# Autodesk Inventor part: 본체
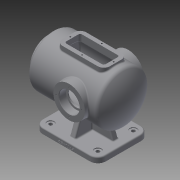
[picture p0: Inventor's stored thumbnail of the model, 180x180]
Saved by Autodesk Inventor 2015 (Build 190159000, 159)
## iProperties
Created: 2021-11
Part Number: 본체
Material: 일반
Document SubType Name: Modeling
Designer: 101698
Mass: 1311.33 g
Surface Area: 2404.16 cm^2
Volume: 1311.33 cm^3
Density: 1 g/cm^3
Appearance: 기본값
Author: 101698
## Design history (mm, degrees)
sketch "스케치1"
  geometry: L1 (-80, -65)-(80, -65); L2 (80, -65)-(80, 65); L3 (80, 65)-(-80, 65); L4 (-80, 65)-(-80, -65); L5 (-80, -65)-(80, 65); L6 (80, -65)-(-80, 65); 1 further point
  constraints: 12 end point, 2 midpoint, 2 parallel, 1 horizontal, 1 perpendicular
  dimensions: "d0" = 160 distance of L1.start L1.end; "d1" = 130 distance of L1.end L2.end
extrude "돌출1" new body sketch "스케치1" distance "d2" = 14; taper "d3" = 0 deg
sketch "스케치2"
  geometry: L1 (-7, -50)-(7, -50); L2 (7, -50)-(7, 50); L3 (7, 50)-(-7, 50); L4 (-7, 50)-(-7, -50); L5 (-7, -50)-(7, 50); L6 (7, -50)-(-7, 50); 1 further point
  constraints: 12 end point, 2 midpoint, 2 parallel, 1 horizontal, 1 perpendicular
  dimensions: "d4" = 14 distance of L2.end L3.end; "d5" = 100 distance of L1.end L2.end
extrude "돌출2" join sketch "스케치2" distance "d6" = 100; taper "d7" = 0 deg
sketch "스케치3"
  geometry: L1 (-7, -50)-(-7, 50) reference; L2 (-7, 50)-(7, 50) reference; L3 (7, 50)-(7, -50) reference; L4 (7, -50)-(-7, -50) reference; L5 (-80, -65)-(-80, 65) reference; L6 (-80, 65)-(80, 65) reference; L7 (80, 65)-(80, -65) reference; L8 (80, -65)-(-80, -65) reference; L9 (-60, -7)-(60, -7); L10 (60, -7)-(60, 7); L11 (60, 7)-(-60, 7); L12 (-60, 7)-(-60, -7); L13 (-60, -7)-(60, 7); L14 (60, -7)-(-60, 7); 1 further point
  constraints: 12 end point, 2 midpoint, 2 parallel, 1 horizontal, 1 perpendicular
  dimensions: "d8" = 14 distance of L11.end L9.start; "d9" = 120 distance of L10.end L11.end
extrude "돌출3" join sketch "스케치3" distance "d10" = 100; taper "d11" = 0 deg
feature "면 기울기1" dims angle "d12" = 20 deg
feature "면 기울기2" dims angle "d13" = 20 deg
feature "면 기울기3" dims angle "d14" = 20 deg
feature "면 기울기4" dims angle "d15" = 20 deg
sketch "스케치8"
  geometry: L1 (-80, 0)-(-80, 14) reference; L2 (-80, 14)-(-60, 14) reference; L3 (-60, 14)-(-23.603, 114) reference; L4 (-23.603, 114)-(23.603, 114) reference; L5 (23.603, 114)-(60, 14) reference; L6 (60, 14)-(80, 14) reference; L7 (80, 14)-(80, 0) reference; L8 (80, 0)-(-80, 0) reference; L9 (-75.993, 179)-(100, 179); L10 (123.314, 91.246)-(-119.568, 136.063); L11 (-109.588, 46.16)-(109.588, 181.84); L12 (-100, 114)-(100, 114); L13 (100, 179)-(100, 114); L14 (80, 0)-(-80, 0) reference; A1 r 95.786 centre (0, 114) between (80, 61.322) and (94.196, 96.619); A2 r 100 centre (0, 114) between (-75.993, 179) and (-100, 114); 2 further points
  constraints: 10 end point, 4 point on circle, 3 midpoint, 3 point on line, 2 centre point, 2 parallel, 1 coincident, 1 horizontal, 1 perpendicular
  dimensions: "d33" = 10 distance of L9.end L11.end; "d34" = 200 distance of L12.start L12.end; "d35" = 65 distance of L9.end L12.end; "d36" = 100 radius of A2; "d142" = 114 vertical distance of L7.end L12.end; "d143" = 20 distance from line of L7 L12.end
revolve "회전1" sketch "스케치8" stored, may be unused: angle "d37" = 90 deg
sketch "스케치10"
  geometry: C1 r 65 at (0, 0) reference; C2 r 47.5 at (0, 0); 1 further point
  constraints: 1 centre point, 1 coincident
  dimensions: "d41" = 95 diameter of C2
extrude "돌출7" join sketch "스케치10" distance "d42" = 10; taper "d43" = 0 deg
sketch "스케치11"
  geometry: C1 r 47.5 at (0, 0) reference; 1 further point
hole "구멍1" sketch "스케치11" at (0, 0) diameter "d44" = 65; stored, may be unused: countersink angle "d48" = 90 deg, drill point angle "d50" = 118 deg; dims "d45" = 6, "d46" = 4, "d47" = 2, "d49" = 40
sketch "스케치12"
  geometry: C1 r 32.5 at (0, 0) reference; 2 further points
  constraints: 1 horizontal alignment
  dimensions: "d51" = 40 distance of C1.centre point (40, 0)
hole "구멍2" sketch "스케치12" at (40, 0) diameter "d52" = 3.242; stored, may be unused: countersink angle "d56" = 90 deg, drill point angle "d58" = 118 deg; dims "d53" = 11, "d54" = 4, "d55" = 2, "d57" = 13
node "작업 평면1"
sketch "스케치13"
  geometry: C1 r 40 at (-17, 114); 1 further point
  constraints: 1 centre point
  dimensions: "d63" = 80 diameter of C1; "d64" = 17 horizontal distance of point (0, 0) C1.centre; "d65" = 114 vertical distance of point (0, 0) C1.centre
extrude "돌출8" join sketch "스케치13" distance "d66" = 150; taper "d67" = 0 deg
node "작업 평면2"
sketch "스케치15"
  geometry: L1 (-60, -30)-(60, -30); L2 (60, -30)-(60, 30); L3 (60, 30)-(-60, 30); L4 (-60, 30)-(-60, -30); L5 (-60, -30)-(60, 30); L6 (60, -30)-(-60, 30); 1 further point
  constraints: 12 end point, 2 midpoint, 2 parallel, 1 horizontal, 1 perpendicular
  dimensions: "d69" = 120 distance of L2.end L3.end; "d70" = 60 distance of L3.end L1.start
extrude "돌출9" join sketch "스케치15" stored distance "d71" = 150; taper "d72" = 0 deg
sketch "스케치16"
  geometry: L1 (-50, -20)-(50, -20); L2 (50, -20)-(50, 20); L3 (50, 20)-(-50, 20); L4 (-50, 20)-(-50, -20); L5 (-50, -20)-(50, 20); L6 (50, -20)-(-50, 20); 1 further point
  constraints: 12 end point, 2 midpoint, 2 parallel, 1 horizontal, 1 perpendicular
  dimensions: "d73" = 100 distance of L2.end L3.end; "d74" = 40 distance of L1.end L2.end
extrude "돌출10" cut sketch "스케치16" distance "d75" = 30; taper "d76" = 0 deg
sketch "스케치17"
  geometry: C1 r 40 at (0, 0) reference; 1 further point
hole "구멍3" sketch "스케치17" at (0, 0) diameter "d77" = 42; stored, may be unused: countersink angle "d81" = 90 deg, drill point angle "d83" = 118 deg; dims "d78" = 11, "d79" = 52, "d80" = 18, "d82" = 13
sketch "스케치18"
  geometry: C1 r 21 at (0, 0) reference; C2 r 40 at (0, 0) reference; C3 r 26 at (0, 0); 1 further point
  constraints: 1 centre point, 1 coincident
  dimensions: "d84" = 52 diameter of C3
extrude "돌출11" cut sketch "스케치18" distance "d85" = 18; taper "d86" = 0 deg
sketch "스케치19"
  geometry: C1 r 26 at (0, 0) reference; 2 further points
  constraints: 1 horizontal alignment
  dimensions: "d87" = 32.5 distance of point (32.5, 0) C1.centre
hole "구멍4" sketch "스케치19" at (32.5, 0) diameter "d88" = 3.242; stored, may be unused: countersink angle "d92" = 90 deg, drill point angle "d94" = 118 deg; dims "d89" = 11, "d90" = 52, "d91" = 18, "d93" = 13
sketch "스케치20"
  geometry: 5 further points
  constraints: 2 horizontal alignment, 1 vertical alignment
  dimensions: "d98" = 25 distance of point (0, 0) point (0, 25); "d99" = 25 distance of point (0, 0) point (0, -25); "d100" = 55 distance of point (0, 0) point (-55, 0); "d101" = 55 distance of point (55, 0) point (0, 0)
hole "구멍5" sketch "스케치20" at (0, 25), (0, -25), (55, 0), (-55, 0) diameter "d102" = 3.242; stored, may be unused: countersink angle "d106" = 90 deg, drill point angle "d108" = 118 deg; dims "d103" = 9, "d104" = 52, "d105" = 18, "d107" = 11
fillet "모깎기1" dims "d109" = 5
fillet "모깎기2" dims "d110" = 15
sketch "스케치21"
  geometry: L1 (-47.261, 49)-(-75.993, 49) reference; L2 (-75.993, 179)-(-60, 179) reference; L3 (-60, 179)-(-60, 184) reference; L4 (-60, 184)-(-56.621, 184) reference; L5 (-56.621, 184)-(-56.621, 173) reference; L6 (-56.621, 173)-(-55, 172.026) reference; L7 (-55, 172.026)-(-53.379, 173) reference; L8 (-53.379, 173)-(-53.379, 184) reference; L9 (-53.379, 184)-(-50, 184) reference; L10 (-50, 184)-(-50, 154) reference; L11 (-50, 154)-(50, 154) reference; L12 (50, 154)-(50, 184) reference; L13 (50, 184)-(53.379, 184) reference; L14 (53.379, 184)-(53.379, 173) reference; L15 (53.379, 173)-(55, 172.026) reference; L16 (55, 172.026)-(56.621, 173) reference; L17 (56.621, 173)-(56.621, 184) reference; L18 (56.621, 184)-(60, 184) reference; L19 (60, 184)-(60, 179) reference; L20 (60, 179)-(100, 179) reference; L21 (100, 179)-(100, 161.5) reference; L22 (100, 161.5)-(110, 161.5) reference; L23 (110, 161.5)-(110, 155.621) reference; L24 (110, 155.621)-(97, 155.621) reference; L25 (97, 155.621)-(96.026, 154) reference; L26 (96.026, 154)-(97, 152.379) reference; L27 (97, 152.379)-(110, 152.379) reference; L28 (110, 152.379)-(110, 146.5) reference; L29 (110, 146.5)-(70, 146.5) reference; L30 (70, 146.5)-(50.472, 114) reference; L31 (50.472, 114)-(70, 81.5) reference; L32 (70, 81.5)-(110, 81.5) reference; L33 (110, 81.5)-(110, 75.621) reference; L34 (110, 75.621)-(97, 75.621) reference; L35 (97, 75.621)-(96.026, 74) reference; L36 (96.026, 74)-(97, 72.379) reference; L37 (97, 72.379)-(110, 72.379) reference; L38 (110, 72.379)-(110, 66.5) reference; L39 (110, 66.5)-(100, 66.5) reference; L40 (100, 66.5)-(100, 49) reference; L41 (100, 49)-(47.261, 49) reference; L42 (47.261, 49)-(60, 14) reference; L43 (60, 14)-(80, 14) reference; L44 (80, 14)-(80, 0) reference; L45 (80, 0)-(-80, 0) reference; L46 (-80, 0)-(-80, 14) reference; L47 (-80, 14)-(-60, 14) reference; L48 (-60, 14)-(-47.261, 49) reference; L49 (85, 114)-(-90, 114); L50 (85, 114)-(85, 169); L51 (85, 169)-(-69.75, 169); C1 r 21 at (-17, 114) reference; A1 r 100 centre (0, 114) between (-75.993, 179) and (-75.993, 49) reference; A2 r 90 centre (0, 114) between (-72.155, 167.793) and (-90, 114); A3 r 3 centre (-69.75, 166) between (-69.75, 169) and (-72.155, 167.793); 2 further points
  constraints: 6 end point, 5 point on circle, 2 centre point, 2 tangent, 1 horizontal, 1 perpendicular, 1 point on line, 1 vertical
  dimensions: "d111" = 10 radial gap between concentric circles of A1 A2; "d112" = 10 distance between parallel lines of L51 L2; "d113" = 15 distance between parallel lines of L21 L50; "d114" = 114 distance between parallel lines of L45 L49; "d116" = 3 radius of A3
revolve "회전2" sketch "스케치21" stored, may be unused: angle "d115" = 90 deg
fillet "모깎기3" dims "d117" = 10
fillet "모깎기4" dims "d118" = 3
fillet "모깎기5" dims "d119" = 10
fillet "모깎기6" dims "d120" = 3
fillet "모깎기7" dims "d121" = 3
fillet "모깎기8" dims "d122" = 3
fillet "모깎기9" dims "d123" = 3
fillet "모깎기10" dims "d124" = 20
sketch "스케치22"
  geometry: A1 r 17 centre (-60, 45) between (-60, 62) and (-77, 45) reference; A2 r 17 centre (-60, -45) between (-77, -45) and (-60, -62) reference; A3 r 17 centre (60, -45) between (60, -62) and (77, -45) reference; 1 further point
hole "구멍6" sketch "스케치22" at (-60, -45), (60, -45), (-60, 45) diameter "d125" = 9; stored, may be unused: countersink angle "d129" = 90 deg, drill point angle "d131" = 118 deg; dims "d126" = 9, "d127" = 18, "d128" = 2, "d130" = 11
sketch "스케치23"
  geometry: A1 r 17 centre (60, 45) between (77, 45) and (60, 62) reference; 1 further point
hole "구멍7" sketch "스케치23" at (60, 45) diameter "d132" = 9; stored, may be unused: countersink angle "d136" = 90 deg, drill point angle "d138" = 118 deg; dims "d133" = 9, "d134" = 18, "d135" = 2, "d137" = 11
sketch "스케치24"
  geometry: L1 (0, 0)-(120, 0) reference; 4 further points
  constraints: 2 midpoint, 2 vertical alignment, 1 other
  dimensions: "d139" = 5 distance of point (60, 0) point (60, 5)
feature "엠보싱1" sketch "스케치24" dims "d140" = 0.5, "d141" = 0
fillet "모깎기11" dims "d144" = 0.3
chamfer "모따기1" distance "d145" = 1; stored, may be unused: second distance "d146" = 2, angle "d147" = 45 deg
node "솔리드1"
pattern_circular "원형 패턴1" dims angle "d60" = 360 deg
pattern_circular "원형 패턴2" dims angle "d96" = 360 deg
mirror "대칭1"
node "절단 모서리 투영1"
node "절단 모서리 투영4"
node "절단 모서리 투영5"
other parameters: "d62" = -75, "d68" = 184
